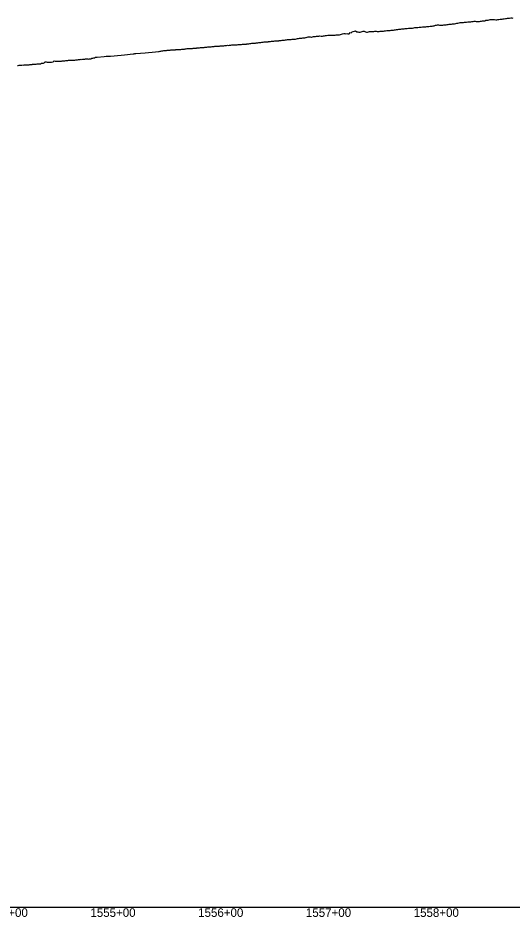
# Model space of a CAD drawing. Extents: x -3793 to 50787, y -1075 to 6138.
# Drawn here: x 42791 to 43250, y 991 to 1825 of the extents above; entities that cross this region are included whole.
import ezdxf

# ---------------------------------------------------------------- set-up
doc = ezdxf.new("R2010")
doc.units = 0
for name, color, linetype in [('RD_DDB_Profile_EX', 7, 'Continuous'), ('RD_DDB_StaTX', 7, 'Continuous'), ('RD_GPK_Profile_Cell', 7, 'Continuous')]:
    doc.layers.add(name, color=color, linetype=linetype)

msp = doc.modelspace()

# ---------------------------------------------------------------- linework, layer by layer
at = {"layer": 'RD_DDB_Profile_EX'}
for points in [[(43179.551985, 1818.393185), (43180.508827, 1818.63128), (43181.466158, 1818.678345), (43182.414297, 1818.43894), (43183.591459, 1818.456945), (43184.549207, 1818.40824), (43185.507443, 1818.455195), (43186.466165, 1818.645745), (43187.415682, 1818.64524), (43188.587086, 1818.706465), (43189.546145, 1819.08875), (43190.50569, 1819.13586), (43191.456113, 1819.470795), (43192.416535, 1819.422165), (43193.582545, 1819.445275), (43194.542973, 1819.78018), (43195.503886, 1819.68345), (43196.455662, 1819.68296), (43197.417448, 1819.92215), (43198.578411, 1820.186955), (43199.540068, 1820.474285), (43200.502209, 1820.66568), (43201.4552, 1820.809385), (43202.418215, 1820.808705), (43203.575009, 1820.875845), (43204.537641, 1820.971205), (43205.50076, 1821.21088), (43206.454722, 1821.258545), (43207.418719, 1821.30596), (43208.571757, 1821.51717), (43209.535312, 1821.564535), (43210.499357, 1821.660055), (43211.454239, 1821.707755), (43212.41917, 1821.80335), (43213.568112, 1821.87534), (43214.5326, 1822.067175), (43215.497582, 1822.162745), (43216.453395, 1822.017715), (43217.419269, 1822.01691), (43218.564798, 1821.811335), (43219.530233, 1821.955215), (43220.496166, 1822.09917), (43221.452924, 1822.14698), (43222.419755, 1822.38754), (43223.561281, 1822.51167), (43224.527734, 1822.51087), (43225.494688, 1822.99287), (43226.452459, 1822.992455), (43227.420316, 1823.23328), (43228.557898, 1823.346685), (43229.525322, 1823.587545), (43230.49325, 1823.63522), (43231.45199, 1823.683165), (43232.420829, 1823.682535), (43233.554477, 1823.643875), (43234.522884, 1823.54642), (43235.490332, 1823.49246), (43236.451651, 1823.734325), (43237.4231, 1823.83058), (43238.545995, 1823.890965), (43239.517022, 1824.035685), (43240.488563, 1824.13197), (43241.450888, 1824.32561), (43242.423357, 1824.37348), (43243.542326, 1824.52604), (43244.514426, 1824.57392), (43245.487044, 1825.01033), (43246.45029, 1824.916455), (43247.422203, 1824.915885), (43248.548306, 1825.13818), (43249.518155, 1825.137455), (43250.480396, 1825.044865)], [(43079.589639, 1809.081975), (43080.532495, 1809.269515), (43081.475847, 1809.17462), (43082.419696, 1809.173875), (43083.652078, 1809.269755), (43084.586587, 1809.17505), (43085.530754, 1809.12715), (43086.475417, 1809.40931), (43087.420578, 1809.40862), (43088.648011, 1809.3859), (43089.583722, 1809.621355), (43090.529102, 1809.715005), (43091.474979, 1809.997565), (43092.421354, 1810.563645), (43093.644212, 1810.62147), (43094.581032, 1810.621135), (43095.527533, 1810.52607), (43096.474533, 1810.62004), (43097.422032, 1810.57221), (43098.644975, 1810.52256), (43099.581348, 1811.655475), (43100.527397, 1811.466055), (43101.473945, 1812.36327), (43102.420992, 1812.741075), (43103.631977, 1812.810105), (43104.578652, 1813.09351), (43105.525826, 1812.24204), (43106.473499, 1812.147005), (43107.421673, 1812.099235), (43108.632747, 1812.112935), (43109.578969, 1812.395975), (43110.52569, 1812.63189), (43111.472911, 1812.962495), (43112.420632, 1812.96221), (43113.628919, 1812.134915), (43114.576267, 1812.086975), (43115.524116, 1812.08634), (43116.472465, 1812.13304), (43117.421316, 1812.55858), (43118.624567, 1812.44796), (43119.576054, 1812.54627), (43120.523446, 1812.687505), (43121.471339, 1812.734185), (43122.419733, 1812.78089), (43123.625337, 1812.791235), (43124.573358, 1812.506485), (43125.52188, 1812.553105), (43126.470905, 1812.694495), (43127.420432, 1812.788575), (43128.6215, 1812.81171), (43129.573674, 1812.86317), (43130.521742, 1812.81507), (43131.470312, 1813.145745), (43132.419384, 1813.334505), (43133.622272, 1813.463115), (43134.570971, 1813.462335), (43135.520173, 1813.651135), (43136.469878, 1813.603), (43137.420087, 1813.791935), (43138.618427, 1813.919895), (43139.571289, 1813.97167), (43140.520035, 1814.112965), (43141.469285, 1814.25434), (43142.409434, 1814.396065), (43143.619201, 1814.52659), (43144.568581, 1814.66798), (43145.518464, 1814.71459), (43146.468852, 1814.903545), (43147.410129, 1814.997985), (43148.614361, 1815.061475), (43149.568237, 1815.11315), (43150.518015, 1815.25463), (43151.468293, 1815.34875), (43152.409459, 1815.348305), (43153.614639, 1815.559295), (43154.565391, 1815.700965), (43155.516642, 1815.74771), (43156.468393, 1815.746975), (43157.411015, 1815.69901), (43158.609854, 1816.01454), (43159.565064, 1816.25635), (43160.516201, 1816.255585), (43161.467835, 1816.30232), (43162.410339, 1816.34937), (43163.609664, 1816.46741), (43164.561754, 1816.466575), (43165.514339, 1816.56086), (43166.467417, 1816.79792), (43167.411351, 1816.94021), (43168.604946, 1817.01255), (43169.558471, 1817.011715), (43170.512489, 1817.106145), (43171.466999, 1817.200625), (43172.412348, 1817.2478), (43173.600269, 1817.410055), (43174.555215, 1817.504595), (43175.510652, 1817.646885), (43176.466579, 1817.741535), (43177.41333, 1817.884245), (43178.595633, 1818.393965), (43179.551985, 1818.393185)], [(42995.570747, 1800.4373), (42996.481286, 1800.527445), (42997.393988, 1800.61314), (42998.300901, 1800.653815), (42998.737305, 1800.674435), (42999.651452, 1800.76499), (43000.564701, 1800.805325), (43001.48135, 1800.987625), (43002.40018, 1800.98264), (43003.322592, 1800.977635), (43003.728355, 1801.02156), (43004.639543, 1801.11297), (43005.558757, 1801.24528), (43006.481558, 1801.37811), (43007.406251, 1801.515825), (43008.331437, 1801.65361), (43008.714918, 1801.67983), (43009.639592, 1801.77146), (43010.555587, 1801.8634), (43011.481147, 1801.908915), (43012.407199, 1802.04688), (43013.333744, 1802.138695), (43013.71009, 1802.179155), (43014.627159, 1802.31745), (43015.553708, 1802.363), (43016.480747, 1802.50113), (43017.408279, 1802.59304), (43018.336302, 1802.685005), (43018.705648, 1802.71767), (43019.624051, 1802.902505), (43020.551947, 1802.90183), (43021.480335, 1802.901155), (43022.409214, 1803.039545), (43023.338585, 1803.13164), (43023.70087, 1803.188675), (43024.620723, 1803.280965), (43025.550083, 1803.326585), (43026.479934, 1803.60431), (43027.410275, 1803.65004), (43028.341108, 1803.69579), (43028.696461, 1803.748475), (43029.617637, 1803.79441), (43030.548333, 1803.840035), (43031.47952, 1803.97865), (43032.411197, 1804.07084), (43033.343366, 1804.07007), (43033.6924, 1804.10818), (43034.614779, 1804.247185), (43035.546691, 1804.339375), (43036.479094, 1804.524705), (43037.411989, 1804.617015), (43038.345374, 1804.66281), (43038.68834, 1804.696835), (43039.611922, 1804.742875), (43040.545049, 1804.88178), (43041.478669, 1805.020755), (43042.41278, 1805.066575), (43043.347383, 1805.06579), (43043.684279, 1805.10594), (43044.609064, 1805.19865), (43045.543408, 1805.337695), (43046.478243, 1805.47682), (43047.413571, 1805.47598), (43048.349391, 1805.521835), (43048.680219, 1805.554635), (43049.606207, 1805.69416), (43050.541766, 1806.160375), (43051.477817, 1806.15959), (43052.414362, 1806.299015), (43053.3514, 1806.391765), (43053.676158, 1806.420745), (43054.60335, 1806.56052), (43055.540124, 1806.653265), (43056.477392, 1806.699275), (43057.415153, 1806.79211), (43058.353409, 1806.88499), (43058.672717, 1806.92297), (43059.601117, 1807.29702), (43060.53911, 1807.53043), (43061.477598, 1807.576575), (43062.41658, 1807.575885), (43063.356057, 1807.434575), (43063.668645, 1807.462475), (43064.598247, 1807.55573), (43065.537457, 1807.97697), (43066.47716, 1807.92936), (43067.417359, 1807.928645), (43068.358054, 1808.16259), (43068.664573, 1808.19303), (43069.595378, 1808.28644), (43070.535803, 1808.3796), (43071.476723, 1808.566745), (43072.418138, 1808.28418), (43073.36005, 1808.37741), (43073.660501, 1808.395215), (43074.592509, 1808.58274), (43075.534149, 1808.723035), (43076.476285, 1808.863405), (43077.418917, 1808.956805), (43078.656428, 1809.082445), (43079.589639, 1809.081975)], [(42877.205412, 1789.84123), (42880.620497, 1790.15561), (42890.145724, 1791.030525), (42898.130446, 1791.762315), (42898.95216, 1792.0091), (42899.776001, 1792.06679), (42900.597543, 1792.165335), (42909.196178, 1792.95009), (42918.721405, 1793.816045), (42921.552132, 1794.07239), (42922.347916, 1794.18303), (42923.141054, 1794.309135), (42923.931559, 1794.41111), (42924.773197, 1794.534495), (42925.616547, 1794.74249), (42926.461472, 1794.82852), (42927.306851, 1794.9947), (42928.246632, 1795.037095), (42928.92776, 1795.055965), (42929.775374, 1795.14173), (42930.61248, 1795.223765), (42931.459852, 1795.305765), (42932.307633, 1795.3069), (42933.157517, 1795.43142), (42933.920509, 1795.514195), (42934.767825, 1795.638525), (42935.618372, 1795.63977), (42936.459686, 1795.67962), (42937.309849, 1795.72329), (42937.771859, 1795.74483), (42938.162238, 1795.76288), (42938.910626, 1795.82071), (42939.760521, 1795.85983), (42940.61389, 1795.94593), (42941.466778, 1795.942625), (42942.313235, 1795.982235), (42943.167484, 1796.11113), (42943.8994, 1796.16766), (42944.752585, 1796.24963), (42945.607974, 1796.33181), (42946.465434, 1796.375535), (42947.323837, 1796.50079), (42948.175986, 1796.66918), (42948.884206, 1796.703165), (42949.744588, 1796.746635), (42950.603298, 1796.70022), (42951.464328, 1796.78671), (42952.326539, 1796.869385), (42953.191226, 1796.952295), (42953.879648, 1797.01223), (42954.735608, 1797.013065), (42955.598289, 1797.00937), (42956.46344, 1797.221855), (42956.822313, 1797.27582), (42957.329592, 1797.3519), (42958.198636, 1797.391665), (42958.867347, 1797.429505), (42959.733136, 1797.469045), (42960.602936, 1797.64288), (42961.464012, 1797.683035), (42962.334865, 1797.683225), (42963.208582, 1797.766815), (42963.853327, 1797.849095), (42964.72353, 1797.93213), (42965.597764, 1798.01961), (42966.472, 1798.102985), (42967.340304, 1798.230345), (42968.217333, 1798.273995), (42968.837837, 1798.321315), (42969.71282, 1798.36073), (42970.590786, 1798.400275), (42971.471603, 1798.575995), (42972.354117, 1798.61598), (42973.230626, 1798.78866), (42973.818427, 1798.84049), (42974.702532, 1798.972755), (42975.872766, 1798.96857), (42976.471205, 1798.96825), (42977.358932, 1799.052345), (42978.24995, 1799.09237), (42978.810769, 1799.152745), (42979.691396, 1799.15249), (42980.579674, 1799.23629), (42981.471243, 1799.23126), (42982.364487, 1799.319895), (42983.261196, 1799.448995), (42983.794263, 1799.49617), (42984.68628, 1799.5803), (42985.574047, 1799.75905), (42986.471153, 1799.753955), (42987.371726, 1799.883645), (42988.272625, 1799.92793), (42988.77657, 1799.96188), (42989.674383, 1800.091675), (42990.577005, 1800.090975), (42991.480269, 1800.085835), (42992.377862, 1800.12619), (42993.28484, 1800.17075), (42993.759914, 1800.222035), (42994.663579, 1800.352135), (42995.570747, 1800.4373)], [(42790.653181, 1781.07132), (42791.480321, 1781.195035), (42792.31698, 1781.276965), (42793.151921, 1781.32078), (42793.977655, 1781.41964), (42794.893455, 1781.46743), (42795.648185, 1781.54091), (42796.48534, 1781.50116), (42797.322673, 1781.54076), (42798.158522, 1781.626365), (42798.9794, 1781.62673), (42799.814475, 1781.66643), (42800.642689, 1781.66453), (42801.480489, 1781.791915), (42802.318467, 1781.831795), (42803.157912, 1781.913635), (42803.969315, 1781.97804), (42804.418682, 1782.068685), (42804.809331, 1782.14735), (42805.646771, 1782.312645), (42806.485913, 1782.310475), (42807.325216, 1782.31191), (42808.157816, 1782.351865), (42808.960026, 1782.487625), (42809.798799, 1782.568805), (42810.64057, 1782.696605), (42811.481341, 1782.69396), (42812.322274, 1782.52769), (42813.165045, 1783.071485), (42813.95957, 1783.141385), (42814.800123, 1783.26474), (42815.643914, 1783.392355), (42816.486943, 1784.527665), (42817.323402, 1784.526345), (42818.167298, 1784.105265), (42818.947499, 1784.12743), (42819.790643, 1784.16764), (42820.635735, 1784.081035), (42821.482653, 1784.124275), (42822.33023, 1784.24921), (42823.469135, 1784.377885), (42823.939435, 1784.452225), (42824.789238, 1785.428165), (42825.637103, 1784.959575), (42826.47852, 1784.96039), (42827.329276, 1785.08559), (42828.182238, 1784.998415), (42828.927048, 1785.07866), (42829.780148, 1785.079495), (42830.631292, 1785.16192), (42831.484637, 1785.20189), (42832.338628, 1785.287985), (42833.195027, 1785.370795), (42833.921228, 1785.456085), (42834.766438, 1785.495665), (42835.623759, 1785.58183), (42836.480791, 1785.664295), (42837.338712, 1785.75052), (42838.193216, 1785.84007), (42838.91533, 1785.902985), (42839.772811, 1786.07474), (42840.629877, 1785.989715), (42841.477844, 1785.99429), (42842.519589, 1786.00431), (42843.187149, 1786.037835), (42843.916481, 1786.14543), (42844.774667, 1786.27843), (42845.628576, 1786.363985), (42846.482311, 1786.44952), (42847.325745, 1786.58193), (42848.177661, 1786.709825), (42848.923907, 1786.726385), (42849.7755, 1786.769145), (42850.628198, 1786.73087), (42851.478042, 1786.773555), (42852.327768, 1786.858555), (42853.174664, 1786.86224), (42853.938924, 1787.11629), (42854.778416, 1787.1588), (42855.626246, 1787.158665), (42856.474013, 1786.99544), (42857.320571, 1787.079845), (42858.167192, 1787.206535), (42858.940453, 1787.239635), (42859.789139, 1787.794085), (42860.625452, 1787.920775), (42861.570043, 1788.01558), (42862.313518, 1788.09373), (42863.157323, 1788.767255), (42864.736647, 1788.850685), (42871.09527, 1789.439805), (42873.141822, 1789.628715), (42877.205412, 1789.84123)]]:
    msp.add_lwpolyline(points, dxfattribs=at)
at = {"layer": 'RD_GPK_Profile_Cell'}
msp.add_line((1000, 1000), (46600, 1000), dxfattribs=at)

# ---------------------------------------------------------------- texts
at = {"layer": 'RD_DDB_StaTX'}
for s, p in [('1554+00', (42758.415471, 991)), ('1555+00', (42858.415471, 991)), ('1556+00', (42958.415471, 991)), ('1557+00', (43058.415471, 991)), ('1558+00', (43158.415471, 991))]:
    msp.add_text(s, height=8, dxfattribs=at).set_placement(p)

doc.saveas('drawing.dxf')
